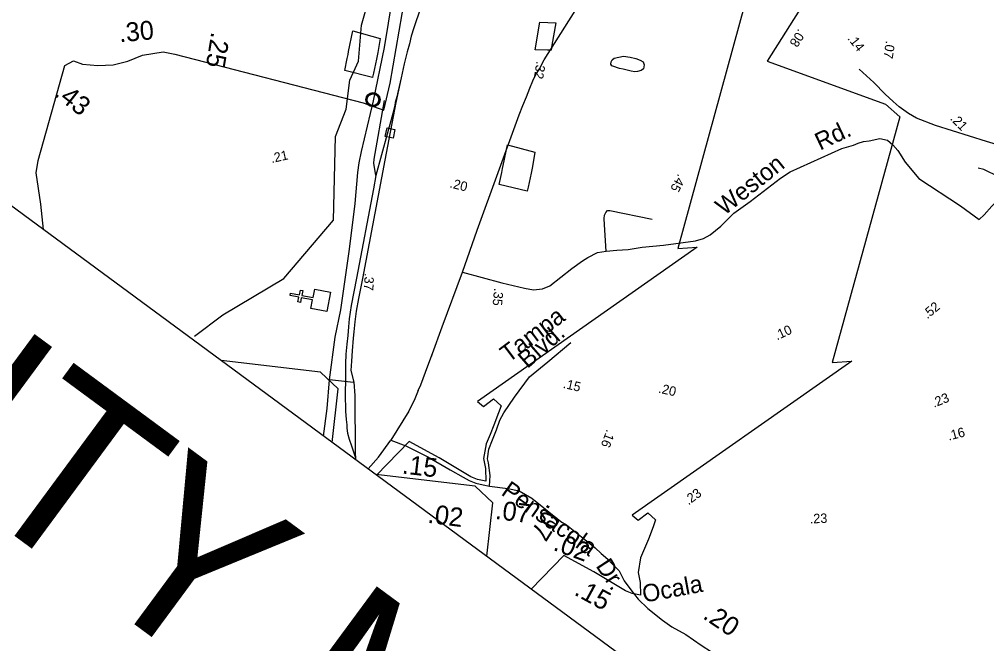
# Model space of a CAD drawing. Extents: x 945666 to 965748, y 644452 to 663300.
# Drawn here: x 952913 to 953745, y 657713 to 658250 of the extents above; entities that cross this region are included whole.
import ezdxf

# ---------------------------------------------------------------- set-up
doc = ezdxf.new("R2010")
doc.units = 0
for name, color, linetype in [('Exist Boundary Political City Limit New', 7, 'Continuous'), ('Exist Civil Demographics Community CELL', 7, 'Continuous'), ('Exist Cultural Church CELL', 7, 'Continuous'), ('Exist Hydrographic Creek Single Shore', 7, 'Continuous'), ('Exist Hydrographic Pond Under 1500 Sq Ft', 7, 'Continuous'), ('Exist Railroad Mainline', 7, 'Continuous'), ('Exist Railroad Station CELL', 7, 'Continuous'), ('Exist Road Primary US Mileage Hundredths English Label', 7, 'Continuous'), ('Exist Road Primary US UnDivided 4 Lane Attributed', 7, 'Continuous'), ('Exist Road Secondary Mileage Tenths English Label', 7, 'Continuous'), ('Exist Road Secondary Type 51 Attributed', 7, 'Continuous'), ('Exist Road Secondary Type 51 Label', 7, 'Continuous'), ('Map Preparation Boundary City Limit Buffer Line', 7, 'Continuous'), ('Old_Level_1', 7, 'Continuous'), ('Old_Level_28', 7, 'Continuous'), ('Old_Level_38', 7, 'Continuous'), ('Sheet Data Field CELL', 7, 'Continuous'), ('Sheet Sticker Preliminary CELL', 7, 'Continuous')]:
    doc.layers.add(name, color=color, linetype=linetype)

msp = doc.modelspace()

# ---------------------------------------------------------------- linework, layer by layer
at = {"layer": 'Exist Boundary Political City Limit New'}
for points in [[(952933.88, 658068.96), (952931.53, 658090.74), (952927.54, 658117.68), (952929.12, 658128.44), (952952.22, 658210.11), (952959.47, 658214.17), (952967.28, 658211.36), (952980.47, 658209.98), (952993.63, 658210.79), (953006.46, 658213.79), (953018.89, 658218.94), (953036.71, 658221.84), (953046.85, 658219.95), (953208.62, 658177.89), (953226.42, 658171.6), (953231.84, 658194.97), (953260.2, 658359.21), (953261.51, 658388.04), (953258.98, 658438.73), (953257.1, 658496.31), (953263.12, 658541.05)], [(953537.38, 658264.09), (953479.25, 658052.67), (953495.96, 658053.92), (953307.17, 657921.18), (953312.32, 657916.88), (953320.78, 657923.41), (953327.39, 657917.34), (953325.2, 657911.34), (953321.2, 657900.69), (953317.86, 657892.6), (953314.4, 657884.6), (953312.34, 657871.9), (953314.02, 657863.48), (953314.22, 657852.46), (953307.16, 657854.03), (953301.34, 657856.27), (953274.17, 657872.66), (953248.34, 657886.64), (953220.32, 657857.7)], [(953216.86, 658199.93), (953192.88, 658205.79), (953195, 658216.15), (953195.71, 658219.59), (953196.24, 658222.2), (953199.85, 658239.8), (953223.41, 658233.47), (953221.47, 658221.35), (953220.33, 658215.56), (953217.63, 658203.42), (953216.88, 658200.01), (953216.86, 658199.93)], [(953182.05, 657885.93), (953187.25, 657931.87), (953172.08, 657946.29), (953086.58, 657956.34)]]:
    msp.add_lwpolyline(points, dxfattribs=at)
at = {"layer": 'Exist Civil Demographics Community CELL'}
msp.add_lwpolyline([(953213.55, 658184.32), (953213.82, 658184.57), (953214.17, 658184.85), (953214.6, 658185.11), (953214.97, 658185.3), (953215.37, 658185.47), (953215.76, 658185.59), (953216.14, 658185.67), (953216.55, 658185.73), (953217.02, 658185.76), (953217.44, 658185.74), (953217.81, 658185.7), (953218.17, 658185.63), (953218.54, 658185.54), (953218.91, 658185.42), (953219.18, 658185.31), (953219.46, 658185.17), (953219.7, 658185.04), (953220.05, 658184.81), (953220.27, 658184.64), (953220.56, 658184.4), (953220.79, 658184.18), (953221.01, 658183.94), (953221.21, 658183.67), (953221.41, 658183.37), (953221.65, 658182.96), (953221.84, 658182.54), (953221.97, 658182.16), (953222.08, 658181.75), (953222.13, 658181.45), (953222.18, 658181.07), (953222.2, 658180.67), (953222.18, 658180.31), (953222.16, 658179.93), (953222.08, 658179.57), (953222, 658179.23), (953221.89, 658178.9), (953221.78, 658178.61), (953221.6, 658178.26), (953221.45, 658177.99), (953221.23, 658177.66), (953221, 658177.37), (953220.75, 658177.09), (953220.49, 658176.84), (953220.17, 658176.58), (953219.84, 658176.35), (953219.53, 658176.17), (953219.13, 658175.98), (953218.76, 658175.83), (953218.4, 658175.72), (953217.99, 658175.63), (953217.52, 658175.58), (953217.1, 658175.56), (953216.71, 658175.57), (953216.38, 658175.6), (953215.9, 658175.7), (953215.43, 658175.83), (953215.06, 658175.98), (953214.66, 658176.17), (953214.41, 658176.32), (953214.17, 658176.48), (953213.88, 658176.69), (953213.67, 658176.88), (953213.4, 658177.13), (953213.14, 658177.43), (953212.95, 658177.68), (953212.76, 658177.97), (953212.59, 658178.25), (953212.47, 658178.52), (953212.28, 658179), (953212.15, 658179.44), (953212.07, 658179.86), (953212.02, 658180.29), (953212.01, 658180.62), (953212.01, 658180.95), (953212.07, 658181.48), (953212.12, 658181.73), (953212.18, 658182.01), (953212.36, 658182.53), (953212.55, 658182.96), (953212.72, 658183.26), (953212.94, 658183.6), (953213.12, 658183.85), (953213.4, 658184.16)], close=True, dxfattribs=at)
for centre, radius in [((953217.13, 658180.67), 6.13), ((953217.13, 658180.7), 4.98)]:
    msp.add_circle(centre, radius, dxfattribs=at)
at = {"layer": 'Exist Cultural Church CELL'}
msp.add_lwpolyline([(953163.78, 658001.14), (953165.23, 658008.39), (953155.53, 658010.35), (953154.71, 658006.27), (953152.68, 658006.68), (953153.5, 658010.76), (953145.84, 658012.3), (953146.25, 658014.34), (953153.91, 658012.8), (953154.73, 658016.87), (953156.77, 658016.46), (953155.94, 658012.39), (953165.64, 658010.43), (953167.13, 658017.77), (953180.69, 658015.03), (953177.34, 657998.4)], close=True, dxfattribs=at)
at = {"layer": 'Exist Hydrographic Creek Single Shore'}
msp.add_lwpolyline([(953063.7, 657977.16), (953087.98, 657995.59), (953140.42, 658026.77), (953183.23, 658077.19), (953184.97, 658148.97), (953194.07, 658172.62), (953197.29, 658197.56), (953204.73, 658213.89), (953207.17, 658244.8), (953217.23, 658280.09), (953212.7, 658297.01), (953198, 658318.53), (953195.99, 658342.12), (953231.11, 658419.41), (953229.87, 658423.06), (953237.62, 658438.07), (953241.62, 658450.05), (953235.89, 658498.53), (953214.05, 658554.58), (953198.03, 658558.74), (953194.31, 658566.38), (953182.03, 658581.59), (953178.6, 658591.53), (953177.37, 658599.15)], dxfattribs=at)
at = {"layer": 'Exist Hydrographic Pond Under 1500 Sq Ft'}
msp.add_lwpolyline([(953424.63, 658216.31), (953428.5, 658217.43), (953432.5, 658218.23), (953438.45, 658217.3), (953443.14, 658216.28), (953447.05, 658214.78), (953449.42, 658213.17), (953450.38, 658210.72), (953449.89, 658207.21), (953447.87, 658205.76), (953444.79, 658204.91), (953442.43, 658204.79), (953439.16, 658205.36), (953435.87, 658206.17), (953432.39, 658206.91), (953429.3, 658207.57), (953427.57, 658208.25), (953425.08, 658208.87), (953422.54, 658209.96), (953421.71, 658211.25), (953422, 658213.39), (953423.02, 658214.98), (953424.63, 658216.31)], dxfattribs=at)
at = {"layer": 'Exist Railroad Mainline'}
for points in [[(953496.77, 658849.77), (953439.11, 658766.27), (953434.45, 658759.1), (953428.22, 658747.98), (953424.48, 658740.75), (953419.55, 658730.34), (953416.53, 658722.78), (953415.54, 658719.88), (953330.81, 658473.62), (953263.93, 658277.51), (953252.36, 658242.54), (953250.06, 658235.49), (953248.62, 658228.64), (953246.69, 658221.95), (953244.11, 658211.67), (953241.48, 658199.5)], [(953241.48, 658199.5), (953236.72, 658178.22), (953227.43, 658128.8), (953208.1, 658026.88), (953204.76, 658009.67), (953202.72, 657998.76), (953201.65, 657989.48), (953200.59, 657981.04), (953200.22, 657975.52), (953199.2, 657964.69), (953198.65, 657955.65), (953198.22, 657947.6), (953200.81, 657937.56), (953201.52, 657926.17), (953201.86, 657876.62), (953202.02, 657872.63)], [(953241.48, 658199.5), (953238.74, 658188.26), (953237.77, 658183.24), (953236.35, 658178.18), (953236.08, 658176.02), (953234.35, 658168.9), (953219.74, 658115.36)], [(953219.74, 658115.36), (953217.92, 658126), (953218.2, 658129.66), (953226.99, 658180.11)], [(953219.74, 658115.36), (953217.69, 658104.03), (953202.99, 658027.16), (953198.38, 658003.61), (953196.81, 657992.13), (953196.04, 657985.4), (953195.41, 657977.93), (953194.77, 657970.25), (953193.88, 657961.69), (953193.65, 657953.48), (953193.66, 657940.56), (953193.37, 657927.67), (953193.57, 657912.89), (953194.06, 657905.63), (953194.72, 657901.04), (953194.82, 657898.16), (953195.18, 657893.8), (953196.76, 657888.72), (953198.56, 657882.82), (953202.02, 657872.63)], [(953202.02, 657872.63), (953202.08, 657871.15)]]:
    msp.add_lwpolyline(points, dxfattribs=at)
at = {"layer": 'Exist Railroad Station CELL'}
msp.add_lwpolyline([(953236.02, 658155.01), (953234.52, 658147.58), (953227.75, 658148.95), (953229.25, 658156.37)], close=True, dxfattribs=at)
at = {"layer": 'Exist Road Primary US UnDivided 4 Lane Attributed'}
for points in [[(953217.52, 658179.86), (953227.19, 658225.7), (953244.62, 658332.14), (953250.58, 658367.23), (953252.71, 658395.51)], [(953294.18, 658032.4), (953306.83, 658068.42), (953342.91, 658167.72), (953346.11, 658175.59), (953349.13, 658183.21), (953351.97, 658190.72), (953354.53, 658196.94), (953357.04, 658201.72), (953360.38, 658207.22), (953364.52, 658214.99), (953391, 658257.16), (953414.16, 658293.67), (953430.53, 658319.66), (953456.81, 658360.46)], [(953197.11, 658052.08), (953201.71, 658091.51), (953204.19, 658118.02), (953205.31, 658126.25), (953207.28, 658136.13), (953217.52, 658179.86)], [(953179.75, 657939.67), (953184.79, 657976.53), (953189.5, 658000.02), (953197.11, 658052.08)], [(953267.48, 657959.8), (953268.5, 657962.36), (953276.54, 657985.4), (953294.18, 658032.4)], [(953256.02, 657930.64), (953258.39, 657935.52), (953264.3, 657951.77), (953268.5, 657962.36)], [(953174.71, 657891.34), (953177.79, 657914.94), (953179.75, 657939.67)], [(953256.02, 657930.64), (953253.19, 657923.39), (953248, 657912.67), (953232.48, 657887.83)], [(953213.01, 657863.1), (953221.79, 657873.17), (953232.48, 657887.83)]]:
    msp.add_lwpolyline(points, dxfattribs=at)
at = {"layer": 'Exist Road Secondary Type 51 Attributed'}
msp.add_line((953722.42, 658089.32), (953738.41, 658077.53), dxfattribs=at)
for points in [[(953669.7, 658174.48), (953664.49, 658179.29), (953657.62, 658185.45), (953647.96, 658195.38), (953635.3, 658207.07)], [(953744.78, 658144.81), (953701.03, 658158.54), (953684.69, 658164.85), (953677.75, 658168.78), (953669.7, 658174.48)], [(953417.76, 658050.29), (953426.89, 658051.39), (953436.56, 658051.94), (953448.63, 658053.9), (953467.04, 658055.67), (953494.6, 658059.32), (953501.58, 658061.21), (953507.24, 658064.55), (953516.45, 658071.83), (953527.66, 658083.22), (953541.52, 658092.98), (953567.74, 658113.15), (953576.02, 658118.61), (953620.46, 658138.65), (953630.45, 658141.72), (953634.36, 658143.35), (953639.04, 658144.76), (953643.93, 658145.33), (953653.13, 658147.29), (953659.69, 658145.9), (953664.26, 658141.92), (953668.63, 658136.87), (953675.02, 658126.91), (953686.58, 658112.91), (953722.42, 658089.32)], [(953788.06, 658131.29), (953781.08, 658133.94), (953744.78, 658144.81)], [(953770.57, 658111.52), (953755.57, 658114.42), (953742.6, 658120.58), (953737.62, 658121.71)], [(953738.41, 658077.53), (953742.8, 658081.53), (953749.53, 658089.1), (953770.57, 658111.52)], [(953417.76, 658050.29), (953416.3, 658072.91), (953416.04, 658078.38), (953416.4, 658081.32), (953417.39, 658083.79), (953418.99, 658085.4), (953420.99, 658085.46), (953457.29, 658078.05)], [(953294.18, 658032.4), (953327.91, 658023.19), (953347.38, 658018.59), (953355.13, 658017.19), (953362.93, 658017.99), (953369.16, 658020.59), (953388.21, 658035.48), (953397.5, 658042.22), (953401.93, 658044.86), (953410.38, 658049.18), (953417.76, 658050.29)], [(953317.3, 657848.11), (953317.89, 657857.5), (953316.45, 657868.28), (953315.71, 657871.69), (953316.76, 657880.12), (953319.84, 657888.2), (953323.28, 657896.76), (953326.23, 657904.92), (953329.66, 657911.38), (953338.76, 657924.75), (953351.74, 657942.37), (953367.46, 657955.11), (953387.44, 657971.81)], [(953200.4, 657937.55), (953179.75, 657939.67)], [(953232.48, 657887.83), (953245.36, 657883.06)], [(953245.36, 657883.06), (953256.41, 657877.53), (953264.31, 657873.33), (953283.56, 657862.37), (953294.6, 657855.84), (953299.86, 657853.1), (953305.6, 657850.81), (953312.05, 657849.28), (953317.3, 657848.11)], [(953317.3, 657848.11), (953333.24, 657846.24), (953342.76, 657844.23), (953353.87, 657837.82), (953378.85, 657817.77), (953383.67, 657814.87), (953399.51, 657802.38), (953408.31, 657795.24), (953413.51, 657790.44), (953419.08, 657785.3), (953422.96, 657781.36), (953428.89, 657775.37), (953433.18, 657766.84), (953438.96, 657759.16)], [(953438.96, 657759.16), (953445.12, 657750.94), (953453.65, 657743), (953466.12, 657733.01), (953474.11, 657727.32), (953486.19, 657720.52)], [(953486.19, 657720.52), (953499.42, 657711.55), (953508.35, 657705.64)]]:
    msp.add_lwpolyline(points, dxfattribs=at)
at = {"layer": 'Map Preparation Boundary City Limit Buffer Line'}
for points in [[(953367.15, 658223.19), (953356.62, 658223.68), (953360.55, 658247.28), (953374.53, 658246.81), (953371.13, 658227.56), (953370.39, 658223.34), (953367.93, 658223.21), (953367.15, 658223.19)], [(953349.76, 658101.91), (953325.78, 658107.77), (953327.9, 658118.13), (953328.61, 658121.57), (953329.14, 658124.18), (953332.75, 658141.78), (953356.31, 658135.45), (953354.38, 658123.33), (953353.23, 658117.54), (953350.54, 658105.4), (953349.79, 658101.99), (953349.76, 658101.91)], [(953314.95, 657787.91), (953320.15, 657833.85), (953304.98, 657848.28), (953219.48, 657858.32)]]:
    msp.add_lwpolyline(points, dxfattribs=at)
at = {"layer": 'Old_Level_1'}
for points in [[(953667.37, 661172.93), (956829.74, 658840.64), (955088.61, 656479.82), (951926.24, 658812.1)], [(951728.89, 658544.51), (954891.26, 656212.23), (955088.61, 656479.82), (951926.24, 658812.1)]]:
    msp.add_lwpolyline(points, close=True, dxfattribs=at)
at = {"layer": 'Old_Level_28'}
msp.add_lwpolyline([(953587.66, 658263.81), (953556.16, 658213.89), (953658.09, 658176.79), (953670.28, 658166.08), (953612.15, 657954.65), (953628.87, 657955.9), (953440.08, 657823.17), (953445.22, 657818.87), (953453.68, 657825.39), (953460.29, 657819.32), (953458.1, 657813.32), (953454.1, 657802.67), (953450.76, 657794.58), (953447.3, 657786.58), (953445.25, 657773.89), (953446.92, 657765.46), (953447.13, 657754.44), (953440.06, 657756.01), (953434.24, 657758.25), (953407.08, 657774.65), (953381.24, 657788.63), (953353.22, 657759.69)], dxfattribs=at)

# ---------------------------------------------------------------- texts
at = {"layer": 'Exist Road Primary US Mileage Hundredths English Label'}
for s, height, rotation, p in [('.08', 8.119, 237.20908, (953583.23, 658242.13)), ('.32', 8.119, 260.70011, (953357.87, 658214.12)), ('.45', 8.119, 241.95465, (953479.71, 658117.39)), ('.35', 8.119, 264.65246, (953321.43, 658018.82)), ('.16', 8.119, 249.43012, (953418.29, 657897.48)), ('.07', 16.238, 237.9992, (953368.1, 657833.75))]:
    msp.add_text(s, height=height, rotation=rotation, dxfattribs=at).set_placement(p)
at = {"layer": 'Exist Road Secondary Mileage Tenths English Label'}
for s, height, rotation, p in [('.30', 16.238, 5.23925, (952999.28, 658230.06)), ('.25', 16.238, 260.82826, (953078.23, 658239.46)), ('.14', 8.119, 307.64617, (953624.95, 658233.26)), ('.07', 8.119, 261.05262, (953658.39, 658231.65)), ('.43', 16.238, 321.73132, (952942.26, 658184.56)), ('.21', 8.119, 314.60684, (953713.02, 658163.96)), ('.21', 8.119, 12.73803, (953130.08, 658126.14)), ('.20', 8.119, 346.09316, (953282.63, 658105.28)), ('.37', 8.119, 267.75062, (953209.97, 658031.62)), ('.52', 8.119, 39.53782, (953693.93, 657991.71)), ('.10', 8.119, 24.87525, (953564.66, 657973.62)), ('.15', 8.119, 346.51501, (953380.12, 657932.89)), ('.20', 8.119, 347.13485, (953462.17, 657928.79)), ('.23', 8.119, 22.0647, (953699.61, 657915.65)), ('.16', 8.119, 14.62092, (953712.41, 657887.4)), ('.15', 16.238, 353.44916, (953241.68, 657859.18)), ('.23', 8.119, 36.39015, (953488.45, 657831.62)), ('.02', 16.238, 352.7885, (953263.67, 657816.79)), ('.07', 16.238, 352.7885, (953321.78, 657820.14)), ('.23', 8.119, 1.96462, (953592.97, 657816.17)), ('.15', 16.238, 331.4143, (953389.36, 657755.16)), ('.20', 16.238, 325.96338, (953500.08, 657734.97))]:
    msp.add_text(s, height=height, rotation=rotation, dxfattribs=at).set_placement(p)
at = {"layer": 'Exist Road Secondary Type 51 Label'}
for s, rotation, p in [('Rd.', 25.33357, (953601.69, 658136.84)), ('Weston', 38.53379, (953519.28, 658080.57)), ('Tampa', 36.96979, (953333.76, 657953.98)), ('Blvd.', 41.0695, (953349.99, 657948.91)), ('Pensacola', 324.80956, (953326.56, 657841.35)), ('Dr.', 303.26352, (953408.36, 657779.67)), ('Ocala', 10.48435, (953450.21, 657747.97))]:
    msp.add_text(s, height=15, rotation=rotation, dxfattribs=at).set_placement(p)
at = {"layer": 'Old_Level_38'}
msp.add_text('VICINITY MAP', height=150, rotation=323.59084, dxfattribs=at).set_placement((952391.64, 658186.9))
at = {"layer": 'Sheet Data Field CELL'}
for s, p in [('1. DESIGN EXCEPTIONS FOR VERTICAL CURVE K VALUE', (951636.01, 658445.97)), (' AND STOPPING SIGHT DISTANCE HAVE BEEN REQUESTED', (951567.93, 658353.65))]:
    msp.add_text(s, height=87.501, rotation=323.59084, dxfattribs=at).set_placement(p)
at = {"layer": 'Sheet Sticker Preliminary CELL'}
msp.add_text('.02', height=16.238, rotation=339.67516, dxfattribs=at).set_placement((953371.33, 657793.49))

doc.saveas('drawing.dxf')
